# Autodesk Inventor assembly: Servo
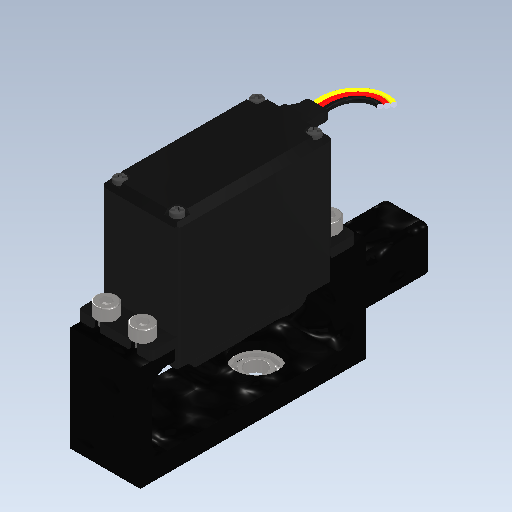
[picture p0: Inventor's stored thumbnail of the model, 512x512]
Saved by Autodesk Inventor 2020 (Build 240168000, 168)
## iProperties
Created: 2023-10
Part Number: Servo
Document SubType Name: Assembly
Designer: bruno
Mass: 43.2666 g
Surface Area: 136.979 cm^2
Volume: 39.4026 cm^3
Density: 1.09807 g/cm^3
Author: bruno
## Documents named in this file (5)
- C:\Users\bruno\Documents\1-Cours-2023-24\Maquettes-Inventor\Pince-robot-Dobot\Servo.iam
- C:\Users\bruno\Documents\1-Cours-2023-24\Maquettes-Inventor\Pince-robot-Dobot\HS422\corps_HS422.ipt
- C:\Users\bruno\Documents\1-Cours-2023-24\Maquettes-Inventor\Pince-robot-Dobot\support-servo.ipt
- C:\Users\bruno\Documents\1-Cours-2023-24\Maquettes-Inventor\Pince-robot-Dobot\HS422\Servo\Design Accelerator\Roulement1.iam
- C:\Users\bruno\Documents\Inventor\Content Center Files\R2020\fr-FR\KS B 1003\KS B 1003 - M 3 x 6.ipt
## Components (7 placed, 4 different names)
1. corps_HS422:1 — Placage:1, Placage:2, Affleurement:1, Logement:1, Logement:2, Logement:3, Logement:4
2. support-servo:1 — Placage:1, Placage:2, Affleurement:1, Placage:3, Affleurement:2
3. Roulement:1 [sub-assembly] — Placage:3, Affleurement:2
4. KS B 1003 - Métrique M 3 x 6:1 — Logement:2
5. KS B 1003 - Métrique M 3 x 6:2 — Logement:4
6. KS B 1003 - Métrique M 3 x 6:3 — Logement:3
7. KS B 1003 - Métrique M 3 x 6:4 — Logement:1
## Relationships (9: Insert 4, Mate 3, Flush 2)
- Placage:1 [Mate]: corps_HS422:1 ↔ support-servo:1
- Placage:2 [Mate]: corps_HS422:1 ↔ support-servo:1
- Affleurement:1 [Flush]: corps_HS422:1 ↔ support-servo:1
- Placage:3 [Mate]: support-servo:1 ↔ Roulement:1
- Affleurement:2 [Flush]: support-servo:1 ↔ Roulement:1
- Logement:1 [Insert]: corps_HS422:1 ↔ KS B 1003 - Métrique M 3 x 6:4
- Logement:2 [Insert]: corps_HS422:1 ↔ KS B 1003 - Métrique M 3 x 6:1
- Logement:3 [Insert]: corps_HS422:1 ↔ KS B 1003 - Métrique M 3 x 6:3
- Logement:4 [Insert]: corps_HS422:1 ↔ KS B 1003 - Métrique M 3 x 6:2
